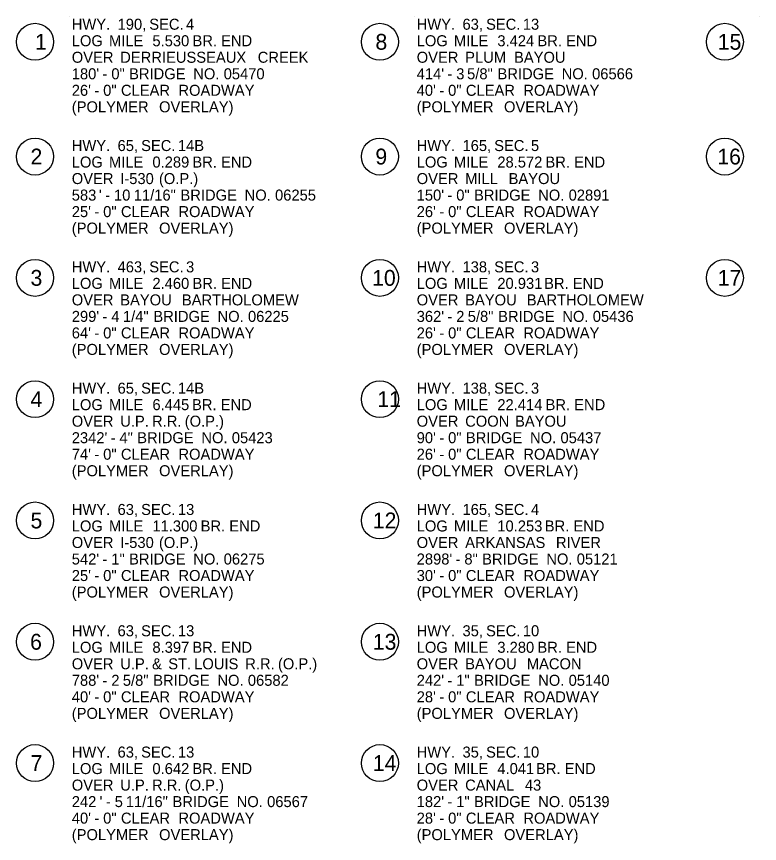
# Model space of a CAD drawing. Extents: x 3046 to 131673, y -8885 to 10756.
# Drawn here: x 25258 to 33696, y -8726 to 662 of the extents above; entities that cross this region are included whole.
import ezdxf

# ---------------------------------------------------------------- set-up
doc = ezdxf.new("R2010")
doc.units = 0
for name, color, linetype in [('Default', 7, 'Continuous'), ('R_Annotation', 7, 'Continuous'), ('R_Border Notes', 7, 'Continuous')]:
    doc.layers.add(name, color=color, linetype=linetype)

msp = doc.modelspace()

# ---------------------------------------------------------------- linework, layer by layer
at = {"layer": 'R_Annotation'}
for centre in [(25467.6, 374.8), (29385.3, 374.8), (33303, 374.8), (25467.6, -927.9), (29385.3, -927.9), (33303, -927.9), (25467.6, -2305.1), (29385.3, -2305.1), (33303, -2305.1), (25467.6, -3682.3), (29385.3, -3682.3), (25467.6, -5059.5), (29385.3, -5059.5), (25467.6, -6436.7), (29385.3, -6436.7), (25467.6, -7813.9), (29385.3, -7813.9)]:
    msp.add_circle(centre, 210, dxfattribs=at)
at = {"layer": 'R_Border Notes'}
for p, q in [((25860.7, 661.8), (25860.7, 661.8)), ((29778.4, 661.8), (29778.4, 661.8)), ((33696.1, 661.8), (33696.1, 661.8))]:
    msp.add_line(p, q, dxfattribs=at)

# ---------------------------------------------------------------- texts
at = {"layer": 'Default'}
for s, p in [('HWY.', (25885, 511.8)), (' 190,', (26358.9, 511.8)), (' SEC.', (26718.8, 511.8)), (' 4', (27136.4, 511.8)), ('HWY.', (29802.8, 511.8)), (' 63,', (30276.6, 511.8)), (' SEC.', (30544.2, 511.8)), (' 13', (30961.8, 511.8)), ('LOG', (25885, 324.3)), (' MILE', (26261.6, 324.3)), (' 5.530', (26754.6, 324.3)), (' BR.', (27209.7, 324.3)), (' END', (27535.1, 324.3)), ('LOG', (29802.8, 324.3)), (' MILE', (30179.4, 324.3)), (' 3.424', (30672.4, 324.3)), (' BR.', (31127.6, 324.3)), (' END', (31453, 324.3)), ('OVER', (25885, 136.8)), (' DERRIEUSSEAUX', (26389.1, 136.8)), (' CREEK', (27950.6, 136.8)), ('OVER', (29802.8, 136.8)), (' PLUM', (30306.9, 136.8)), (' BAYOU', (30861.9, 136.8)), ("180'", (25885, -50.7)), (' -', (26187.5, -50.7)), (' 0"', (26287.9, -50.7)), (' BRIDGE', (26489.6, -50.7)), (' NO.', (27218.5, -50.7)), (' 05470', (27564.2, -50.7)), ("414'", (29802.8, -50.7)), (' -', (30105.3, -50.7)), (' 3', (30205.6, -50.7)), (' 5/8"', (30328.7, -50.7)), (' BRIDGE', (30674.1, -50.7)), (' NO.', (31403, -50.7)), (' 06566', (31748.8, -50.7)), ("26'", (25885, -238.2)), (' -', (26095.2, -238.2)), (' 0"', (26195.5, -238.2)), (' CLEAR', (26397.2, -238.2)), (' ROADWAY', (27050, -238.2)), ("40'", (29802.8, -238.2)), (' -', (30012.9, -238.2)), (' 0"', (30113.3, -238.2)), (' CLEAR', (30314.9, -238.2)), (' ROADWAY', (30967.7, -238.2)), ('(POLYMER', (25885, -425.7)), (' OVERLAY)', (26830.1, -425.7)), ('(POLYMER', (29802.8, -425.7)), (' OVERLAY)', (30747.9, -425.7)), ('HWY.', (25885, -865.4)), (' 65,', (26358.9, -865.4)), (' SEC.', (26626.4, -865.4)), (' 14B', (27044.1, -865.4)), ('HWY.', (29802.8, -865.4)), (' 165,', (30276.6, -865.4)), (' SEC.', (30636.5, -865.4)), (' 5', (31054.2, -865.4)), ('LOG', (25885, -1052.9)), (' MILE', (26261.6, -1052.9)), (' 0.289', (26754.6, -1052.9)), (' BR.', (27208.4, -1052.9)), (' END', (27533.8, -1052.9)), ('LOG', (29802.8, -1052.9)), (' MILE', (30179.4, -1052.9)), (' 28.572', (30672.4, -1052.9)), (' BR.', (31218.7, -1052.9)), (' END', (31544.1, -1052.9)), ('OVER', (25885, -1240.4)), (' I-530', (26389.1, -1240.4)), (' (O.P.)', (26828.7, -1240.4)), ('OVER', (29802.8, -1240.4)), (' MILL', (30306.9, -1240.4)), (' BAYOU', (30800.2, -1240.4)), ('583', (25885, -1427.9)), (" '", (26146.7, -1427.9)), (' 10', (26318.6, -1427.9)), (' 11/16"', (26542.9, -1427.9)), (' BRIDGE', (27072.9, -1427.9)), (' NO.', (27801.9, -1427.9)), (' 06255', (28147.6, -1427.9)), ("150'", (29802.8, -1427.9)), (' 0"', (30205.6, -1427.9)), (' BRIDGE', (30407.3, -1427.9)), (' NO.', (31136.2, -1427.9)), (' 02891', (31482, -1427.9)), (' -', (26218.3, -1427.9)), (' -', (30105.3, -1427.9)), ("25'", (25885, -1615.4)), (' 0"', (26195.5, -1615.4)), (' CLEAR', (26397.2, -1615.4)), (' ROADWAY', (27050, -1615.4)), ("26'", (29802.8, -1615.4)), (' 0"', (30113.3, -1615.4)), (' CLEAR', (30314.9, -1615.4)), (' ROADWAY', (30967.7, -1615.4)), (' -', (26095.2, -1615.4)), (' -', (30012.9, -1615.4)), ('(POLYMER', (25885, -1802.9)), (' OVERLAY)', (26830.1, -1802.9)), ('(POLYMER', (29802.8, -1802.9)), (' OVERLAY)', (30747.9, -1802.9)), ('HWY.', (25885, -2242.6)), (' 463,', (26358.9, -2242.6)), (' SEC.', (26718.8, -2242.6)), (' 3', (27136.4, -2242.6)), ('HWY.', (29802.8, -2242.6)), (' 138,', (30276.6, -2242.6)), (' SEC.', (30636.5, -2242.6)), (' 3', (31054.2, -2242.6)), ('LOG', (25885, -2430.1)), (' MILE', (26261.6, -2430.1)), (' 2.460', (26754.6, -2430.1)), (' BR.', (27209.7, -2430.1)), (' END', (27535.1, -2430.1)), ('LOG', (29802.8, -2430.1)), (' MILE', (30179.4, -2430.1)), (' 20.931', (30672.4, -2430.1)), (' BR.', (31203.7, -2430.1)), (' END', (31529.1, -2430.1)), ('OVER', (25885, -2617.6)), (' BAYOU', (26389.1, -2617.6)), (' BARTHOLOMEW', (27089.4, -2617.6)), ('OVER', (29802.8, -2617.6)), (' BAYOU', (30306.9, -2617.6)), (' BARTHOLOMEW', (31007.1, -2617.6)), ("299'", (25885, -2805.1)), (' 4', (26287.9, -2805.1)), (' 1/4"', (26420, -2805.1)), (' BRIDGE', (26765.3, -2805.1)), (' NO.', (27494.3, -2805.1)), (' 06225', (27840, -2805.1)), ("362'", (29802.8, -2805.1)), (' 2', (30205.6, -2805.1)), (' 5/8"', (30336.4, -2805.1)), (' BRIDGE', (30681.8, -2805.1)), (' NO.', (31410.7, -2805.1)), (' 05436', (31756.4, -2805.1)), (' -', (26187.5, -2805.1)), (' -', (30105.3, -2805.1)), ("64'", (25885, -2992.6)), (' 0"', (26195.5, -2992.6)), (' CLEAR', (26397.2, -2992.6)), (' ROADWAY', (27050, -2992.6)), ("26'", (29802.8, -2992.6)), (' 0"', (30113.3, -2992.6)), (' CLEAR', (30314.9, -2992.6)), (' ROADWAY', (30967.7, -2992.6)), (' -', (26095.2, -2992.6)), (' -', (30012.9, -2992.6)), ('(POLYMER', (25885, -3180.1)), (' OVERLAY)', (26830.1, -3180.1)), ('(POLYMER', (29802.8, -3180.1)), (' OVERLAY)', (30747.9, -3180.1)), ('HWY.', (25885, -3619.8)), (' 65,', (26358.9, -3619.8)), (' SEC.', (26626.4, -3619.8)), (' 14B', (27044.1, -3619.8)), ('HWY.', (29802.8, -3619.8)), (' 138,', (30276.6, -3619.8)), (' SEC.', (30636.5, -3619.8)), (' 3', (31054.2, -3619.8)), ('LOG', (25885, -3807.3)), (' MILE', (26261.6, -3807.3)), (' 6.445', (26754.6, -3807.3)), (' BR.', (27204.1, -3807.3)), (' END', (27529.5, -3807.3)), ('LOG', (29802.8, -3807.3)), (' MILE', (30179.4, -3807.3)), (' 22.414', (30672.4, -3807.3)), (' BR.', (31220, -3807.3)), (' END', (31545.4, -3807.3)), ('OVER', (25885, -3994.8)), (' U.P.', (26389.1, -3994.8)), (' R.R.', (26750.3, -3994.8)), (' (O.P.)', (27121.8, -3994.8)), ('OVER', (29802.8, -3994.8)), (' COON', (30306.9, -3994.8)), (' BAYOU', (30873.3, -3994.8)), ("2342'", (25885, -4182.3)), (' -', (26279.9, -4182.3)), (' 4"', (26380.2, -4182.3)), (' BRIDGE', (26581.9, -4182.3)), (' NO.', (27310.8, -4182.3)), (' 05423', (27656.6, -4182.3)), ("90'", (29802.8, -4182.3)), (' -', (30012.9, -4182.3)), (' 0"', (30113.3, -4182.3)), (' BRIDGE', (30314.9, -4182.3)), (' NO.', (31043.9, -4182.3)), (' 05437', (31389.6, -4182.3)), ("74'", (25885, -4369.8)), (' -', (26095.2, -4369.8)), (' 0"', (26195.5, -4369.8)), (' CLEAR', (26397.2, -4369.8)), (' ROADWAY', (27050, -4369.8)), ("26'", (29802.8, -4369.8)), (' -', (30012.9, -4369.8)), (' 0"', (30113.3, -4369.8)), (' CLEAR', (30314.9, -4369.8)), (' ROADWAY', (30967.7, -4369.8)), ('(POLYMER', (25885, -4557.3)), (' OVERLAY)', (26830.1, -4557.3)), ('(POLYMER', (29802.8, -4557.3)), (' OVERLAY)', (30747.9, -4557.3)), ('HWY.', (25885, -4997)), (' 63,', (26358.9, -4997)), (' SEC.', (26626.4, -4997)), (' 13', (27044.1, -4997)), ('HWY.', (29802.8, -4997)), (' 165,', (30276.6, -4997)), (' SEC.', (30636.5, -4997)), (' 4', (31054.2, -4997)), ('LOG', (25885, -5184.5)), (' MILE', (26261.6, -5184.5)), (' 11.300', (26754.6, -5184.5)), (' BR.', (27302.1, -5184.5)), (' END', (27627.4, -5184.5)), ('LOG', (29802.8, -5184.5)), (' MILE', (30179.4, -5184.5)), (' 10.253', (30672.4, -5184.5)), (' BR.', (31211, -5184.5)), (' END', (31536.4, -5184.5)), ('OVER', (25885, -5372)), (' I-530', (26389.1, -5372)), (' (O.P.)', (26828.7, -5372)), ('OVER', (29802.8, -5372)), (' ARKANSAS', (30306.9, -5372)), (' RIVER', (31338.1, -5372)), ("542'", (25885, -5559.5)), (' 1"', (26287.9, -5559.5)), (' BRIDGE', (26489.6, -5559.5)), (' NO.', (27218.5, -5559.5)), (' 06275', (27564.2, -5559.5)), ("2898'", (29802.8, -5559.5)), (' 8"', (30298, -5559.5)), (' BRIDGE', (30499.6, -5559.5)), (' NO.', (31228.6, -5559.5)), (' 05121', (31574.3, -5559.5)), (' -', (26187.5, -5559.5)), (' -', (30197.6, -5559.5)), ("25'", (25885, -5747)), (' 0"', (26195.5, -5747)), (' CLEAR', (26397.2, -5747)), (' ROADWAY', (27050, -5747)), ("30'", (29802.8, -5747)), (' 0"', (30113.3, -5747)), (' CLEAR', (30314.9, -5747)), (' ROADWAY', (30967.7, -5747)), (' -', (26095.2, -5747)), (' -', (30012.9, -5747)), ('(POLYMER', (25885, -5934.5)), (' OVERLAY)', (26830.1, -5934.5)), ('(POLYMER', (29802.8, -5934.5)), (' OVERLAY)', (30747.9, -5934.5)), ('HWY.', (25885, -6374.2)), (' 63,', (26358.9, -6374.2)), (' SEC.', (26626.4, -6374.2)), (' 13', (27044.1, -6374.2)), ('HWY.', (29802.8, -6374.2)), (' 35,', (30276.6, -6374.2)), (' SEC.', (30544.2, -6374.2)), (' 10', (30961.8, -6374.2)), ('LOG', (25885, -6561.7)), (' MILE', (26261.6, -6561.7)), (' 8.397', (26754.6, -6561.7)), (' BR.', (27208, -6561.7)), (' END', (27533.4, -6561.7)), ('LOG', (29802.8, -6561.7)), (' MILE', (30179.4, -6561.7)), (' 3.280', (30672.4, -6561.7)), (' BR.', (31127.4, -6561.7)), (' END', (31452.8, -6561.7)), ('OVER', (25885, -6749.2)), (' U.P.', (26389.1, -6749.2)), (' &', (26750.3, -6749.2)), (' ST.', (26934.5, -6749.2)), (' LOUIS', (27229.1, -6749.2)), (' R.R.', (27809, -6749.2)), (' (O.P.)', (28180.5, -6749.2)), ('OVER', (29802.8, -6749.2)), (' BAYOU', (30306.9, -6749.2)), (' MACON', (31007.1, -6749.2)), ("788'", (25885, -6936.7)), (' 2', (26287.9, -6936.7)), (' 5/8"', (26418.7, -6936.7)), (' BRIDGE', (26764, -6936.7)), (' NO.', (27493, -6936.7)), (' 06582', (27838.7, -6936.7)), ("242'", (29802.8, -6936.7)), (' 1"', (30205.6, -6936.7)), (' BRIDGE', (30407.3, -6936.7)), (' NO.', (31136.2, -6936.7)), (' 05140', (31482, -6936.7)), (' -', (26187.5, -6936.7)), (' -', (30105.3, -6936.7)), ("40'", (25885, -7124.2)), (' 0"', (26195.5, -7124.2)), (' CLEAR', (26397.2, -7124.2)), (' ROADWAY', (27050, -7124.2)), ("28'", (29802.8, -7124.2)), (' 0"', (30113.3, -7124.2)), (' CLEAR', (30314.9, -7124.2)), (' ROADWAY', (30967.7, -7124.2)), (' -', (26095.2, -7124.2)), (' -', (30012.9, -7124.2)), ('(POLYMER', (25885, -7311.7)), (' OVERLAY)', (26830.1, -7311.7)), ('(POLYMER', (29802.8, -7311.7)), (' OVERLAY)', (30747.9, -7311.7)), ('HWY.', (25885, -7751.4)), (' 63,', (26358.9, -7751.4)), (' SEC.', (26626.4, -7751.4)), (' 13', (27044.1, -7751.4)), ('HWY.', (29802.8, -7751.4)), (' 35,', (30276.6, -7751.4)), (' SEC.', (30544.2, -7751.4)), (' 10', (30961.8, -7751.4)), ('LOG', (25885, -7938.9)), (' MILE', (26261.6, -7938.9)), (' 0.642', (26754.6, -7938.9)), (' BR.', (27208.6, -7938.9)), (' END', (27534, -7938.9)), ('LOG', (29802.8, -7938.9)), (' MILE', (30179.4, -7938.9)), (' 4.041', (30672.4, -7938.9)), (' BR.', (31111.4, -7938.9)), (' END', (31436.7, -7938.9)), ('OVER', (25885, -8126.4)), (' U.P.', (26389.1, -8126.4)), (' R.R.', (26750.3, -8126.4)), (' (O.P.)', (27121.8, -8126.4)), ('OVER', (29802.8, -8126.4)), (' CANAL', (30306.9, -8126.4)), (' 43', (30984.8, -8126.4)), ('242', (25885, -8313.9)), (" '", (26154.4, -8313.9)), (' -', (26226, -8313.9)), (' 5', (26326.3, -8313.9)), (' 11/16"', (26452.6, -8313.9)), (' BRIDGE', (26982.7, -8313.9)), (' NO.', (27711.6, -8313.9)), (' 06567', (28057.4, -8313.9)), ("182'", (29802.8, -8313.9)), (' -', (30105.3, -8313.9)), (' 1"', (30205.6, -8313.9)), (' BRIDGE', (30407.3, -8313.9)), (' NO.', (31136.2, -8313.9)), (' 05139', (31482, -8313.9)), ("40'", (25885, -8501.4)), (' -', (26095.2, -8501.4)), (' 0"', (26195.5, -8501.4)), (' CLEAR', (26397.2, -8501.4)), (' ROADWAY', (27050, -8501.4)), ("28'", (29802.8, -8501.4)), (' -', (30012.9, -8501.4)), (' 0"', (30113.3, -8501.4)), (' CLEAR', (30314.9, -8501.4)), (' ROADWAY', (30967.7, -8501.4)), ('(POLYMER', (25885, -8688.9)), (' OVERLAY)', (26830.1, -8688.9)), ('(POLYMER', (29802.8, -8688.9)), (' OVERLAY)', (30747.9, -8688.9))]:
    msp.add_text(s, height=125, rotation=360, dxfattribs=at).set_placement(p)
at = {"layer": 'R_Annotation'}
for s, p in [('1', (25467.6, 284.8)), ('8', (29334.3, 284.8)), ('15', (33222.3, 284.8)), ('2', (25416.6, -1017.9)), ('9', (29333.6, -1017.9)), ('16', (33217.3, -1017.9)), ('3', (25416.6, -2395.1)), ('10', (29296.7, -2395.1)), ('17', (33222.3, -2395.1)), ('4', (25416.6, -3772.3)), ('11', (29355.5, -3772.3)), ('5', (25416.6, -5149.5)), ('12', (29304.5, -5149.5)), ('6', (25411.6, -6526.7)), ('13', (29304.5, -6526.7)), ('7', (25416.6, -7903.9)), ('14', (29304.5, -7903.9))]:
    msp.add_text(s, height=180, dxfattribs=at).set_placement(p)

doc.saveas('drawing.dxf')
